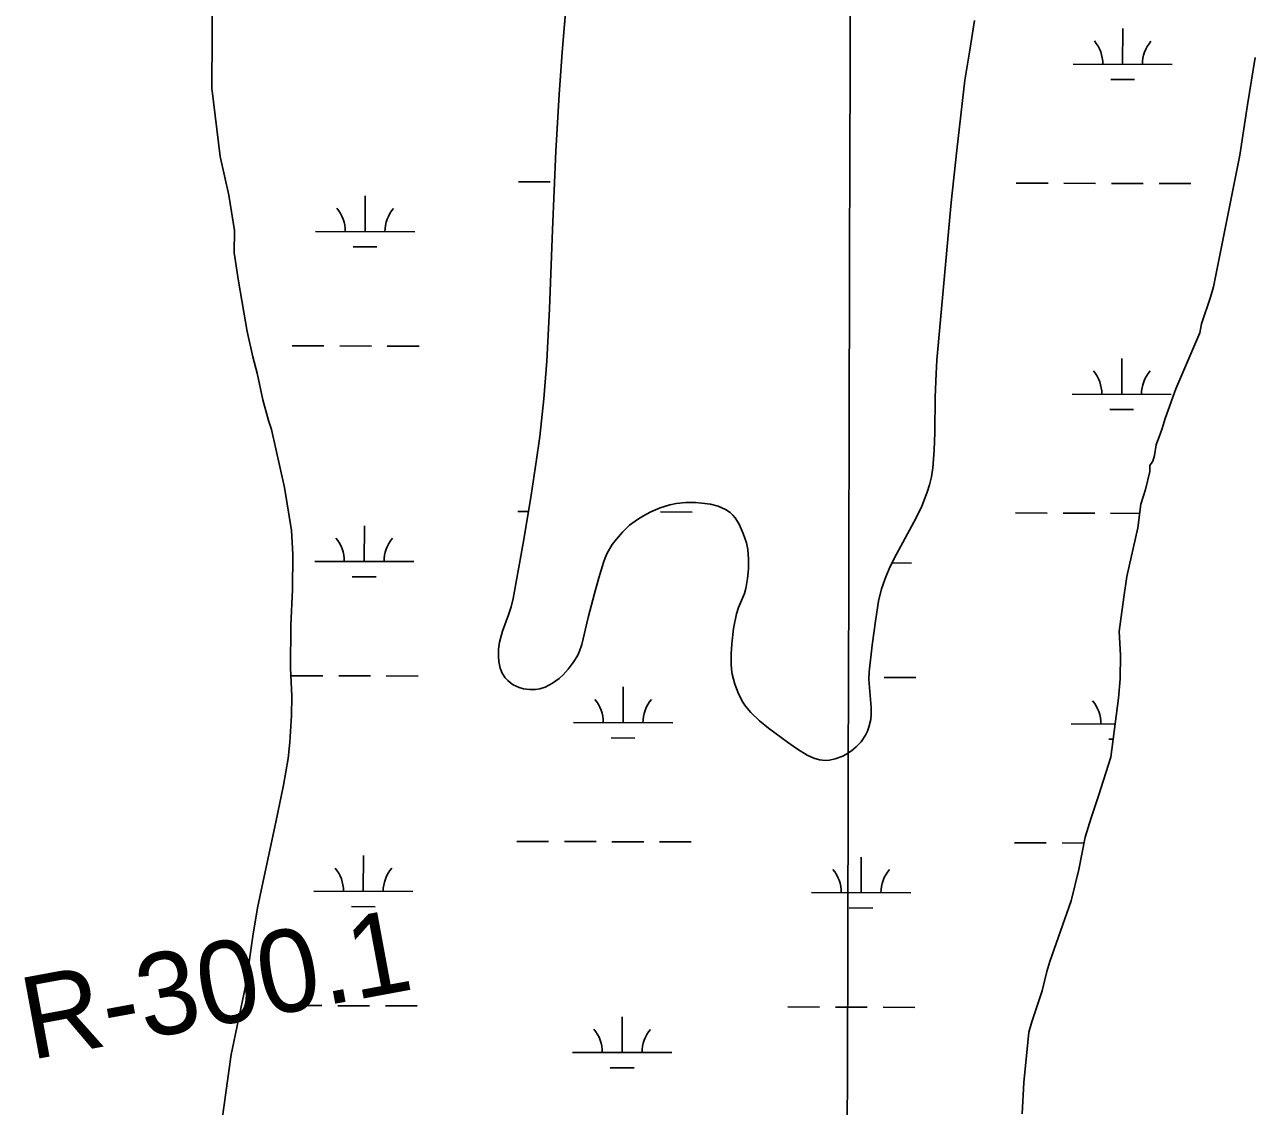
# Model space of a CAD drawing. Extents: x 3161665 to 3199565, y 885729 to 911164.
# Drawn here: x 3180736 to 3181970, y 895619 to 896710 of the extents above; entities that cross this region are included whole.
import ezdxf

# ---------------------------------------------------------------- set-up
doc = ezdxf.new("R2010")
doc.units = 0
for name, color, linetype in [('V-GRID-MAJR', 7, 'Continuous'), ('V-RIVR-RANG-IDEN', 7, 'Continuous'), ('V-SITE-VEGE', 7, 'Continuous'), ('V-TOPO-SHOR', 7, 'Continuous'), ('V-WETL-SWMP', 7, 'Continuous')]:
    doc.layers.add(name, color=color, linetype=linetype)

msp = doc.modelspace()

# ---------------------------------------------------------------- linework, layer by layer
at = {"layer": 'V-GRID-MAJR'}
msp.add_spline([(3181553.2, 891152.2), (3181570, 897211.5), (3181586.7, 903274.3), (3181603.5, 909337.1), (3181603.5, 909340.5)], degree=3, dxfattribs=at)
at = {"layer": 'V-SITE-VEGE'}
for p, q in [((3181278.3, 896682.2), (3181283.8, 896746.3)), ((3181694.2, 896714.2), (3181689.2, 896684.1)), ((3181275.2, 896639.4), (3181278.3, 896682.2)), ((3181689.2, 896684.1), (3181684.4, 896653.9)), ((3181684.4, 896653.9), (3181676.1, 896583.4)), ((3181271.8, 896582.3), (3181275.2, 896639.4)), ((3181268.5, 896502.9), (3181271.8, 896582.3)), ((3181676.1, 896583.4), (3181670.6, 896530.4)), ((3181670.6, 896530.4), (3181656.2, 896371.4)), ((3181265.5, 896423.4), (3181268.5, 896502.9)), ((3181262.8, 896370.5), (3181265.5, 896423.4)), ((3181259.8, 896332.4), (3181262.8, 896370.5)), ((3181656.2, 896371.4), (3181655.3, 896357.9)), ((3181655.3, 896357.9), (3181654.5, 896334.1)), ((3181255.6, 896294.4), (3181259.8, 896332.4)), ((3181654.5, 896334.1), (3181654.1, 896298.4)), ((3181252.2, 896269.1), (3181255.6, 896294.4)), ((3181654.1, 896298.4), (3181653.5, 896280.6)), ((3181653.5, 896280.6), (3181652.1, 896262.8)), ((3181247.1, 896235.4), (3181252.2, 896269.1)), ((3181652.1, 896262.8), (3181650.7, 896253.9)), ((3181648.7, 896245.7), (3181646.4, 896238.2)), ((3181650.7, 896253.9), (3181648.7, 896245.7)), ((3181239.6, 896190.7), (3181247.1, 896235.4)), ((3181646.4, 896238.2), (3181640.9, 896224.3)), ((3181367.6, 896218.5), (3181359.7, 896214.3)), ((3181377.1, 896222.5), (3181367.6, 896218.5)), ((3181386.7, 896225.5), (3181377.1, 896222.5)), ((3181393.3, 896226.8), (3181386.7, 896225.5)), ((3181402.9, 896227.9), (3181393.3, 896226.8)), ((3181412.7, 896228), (3181402.9, 896227.9)), ((3181419.2, 896227.4), (3181412.7, 896228)), ((3181427.8, 896226.1), (3181419.2, 896227.4)), ((3181435.5, 896224.1), (3181427.8, 896226.1)), ((3181442.8, 896220.8), (3181435.5, 896224.1)), ((3181447.5, 896217.7), (3181442.8, 896220.8)), ((3181450.4, 896215.1), (3181447.5, 896217.7)), ((3181640.9, 896224.3), (3181635.2, 896212.5)), ((3181354.1, 896210.9), (3181346.3, 896205)), ((3181359.7, 896214.3), (3181354.1, 896210.9)), ((3181452.8, 896212.4), (3181450.4, 896215.1)), ((3181456.6, 896206.2), (3181452.8, 896212.4)), ((3181460.9, 896196.7), (3181456.6, 896206.2)), ((3181635.2, 896212.5), (3181613.1, 896171.4)), ((3181339, 896198.1), (3181332.9, 896191)), ((3181346.3, 896205), (3181339, 896198.1)), ((3181464.1, 896187.1), (3181460.9, 896196.7)), ((3181229, 896131.1), (3181239.6, 896190.7)), ((3181328.8, 896185.5), (3181323.6, 896176.8)), ((3181332.9, 896191), (3181328.8, 896185.5)), ((3181465.4, 896180.5), (3181464.1, 896187.1)), ((3181321.6, 896172.2), (3181319.9, 896167.5)), ((3181323.6, 896176.8), (3181321.6, 896172.2)), ((3181466.3, 896170.8), (3181465.4, 896180.5)), ((3181466.2, 896161.2), (3181466.3, 896170.8)), ((3181613.1, 896171.4), (3181608, 896160.9)), ((3181319.9, 896167.5), (3181315.3, 896151.9)), ((3181465.3, 896151.2), (3181466.2, 896161.2)), ((3181608, 896160.9), (3181604.7, 896153)), ((3181315.3, 896151.9), (3181310.9, 896136.3)), ((3181463.5, 896141.2), (3181465.3, 896151.2)), ((3181604.7, 896153), (3181600.4, 896140.8)), ((3181310.9, 896136.3), (3181304.4, 896112.1)), ((3181456, 896122.2), (3181462, 896136.3)), ((3181462, 896136.3), (3181463.5, 896141.2)), ((3181600.4, 896140.8), (3181597.4, 896128.4)), ((3181224.2, 896114.5), (3181226.9, 896122.7)), ((3181226.9, 896122.7), (3181229, 896131.1)), ((3181453.9, 896115.7), (3181456, 896122.2)), ((3181597.4, 896128.4), (3181594.5, 896110.6)), ((3181218.2, 896098.2), (3181224.2, 896114.5)), ((3181304.4, 896112.1), (3181298.2, 896084.8)), ((3181451.1, 896100.7), (3181453.9, 896115.7)), ((3181594.5, 896110.6), (3181591, 896084)), ((3181214.9, 896087.2), (3181218.2, 896098.2)), ((3181449.2, 896085.5), (3181451.1, 896100.7)), ((3181213.9, 896080), (3181214.9, 896087.2)), ((3181298.2, 896084.8), (3181295.9, 896078.1)), ((3181448.6, 896075.2), (3181449.2, 896085.5)), ((3181591, 896084), (3181587.9, 896057.3)), ((3181213.9, 896072.5), (3181213.9, 896080)), ((3181214.5, 896067.5), (3181213.9, 896072.5)), ((3181293.6, 896073.4), (3181289.3, 896066.5)), ((3181295.9, 896078.1), (3181293.6, 896073.4)), ((3181448.6, 896064.8), (3181448.6, 896075.2)), ((3181215.9, 896061), (3181214.5, 896067.5)), ((3181217.8, 896055.9), (3181215.9, 896061)), ((3181284.3, 896059.8), (3181279.3, 896054.1)), ((3181289.3, 896066.5), (3181284.3, 896059.8)), ((3181449, 896059.8), (3181448.6, 896064.8)), ((3181449.8, 896054.8), (3181449, 896059.8)), ((3181587.9, 896057.3), (3181587.5, 896049.3)), ((3181220.7, 896051.2), (3181217.8, 896055.9)), ((3181223.4, 896048.3), (3181220.7, 896051.2)), ((3181226.2, 896046), (3181223.4, 896048.3)), ((3181229, 896044.1), (3181226.2, 896046)), ((3181268.5, 896045.7), (3181261.1, 896041.8)), ((3181275.2, 896050.4), (3181268.5, 896045.7)), ((3181279.3, 896054.1), (3181275.2, 896050.4)), ((3181452.5, 896044.8), (3181449.8, 896054.8)), ((3181455.7, 896036), (3181452.5, 896044.8)), ((3181587.5, 896049.3), (3181589.8, 896021.3)), ((3181234.9, 896041.4), (3181229, 896044.1)), ((3181239.1, 896040.1), (3181234.9, 896041.4)), ((3181245.2, 896039.2), (3181239.1, 896040.1)), ((3181251.5, 896039.2), (3181245.2, 896039.2)), ((3181255.7, 896039.9), (3181251.5, 896039.2)), ((3181261.1, 896041.8), (3181255.7, 896039.9)), ((3181459.8, 896027.7), (3181455.7, 896036)), ((3181463.1, 896022.5), (3181459.8, 896027.7)), ((3181468.4, 896016), (3181463.1, 896022.5)), ((3181589.8, 896021.3), (3181589.8, 896014.3)), ((3181477.1, 896007.6), (3181468.4, 896016)), ((3181589.4, 896009.1), (3181587.6, 896001.2)), ((3181589.8, 896014.3), (3181589.4, 896009.1)), ((3181486.2, 896000.2), (3181477.1, 896007.6)), ((3181505.5, 895986.1), (3181486.2, 896000.2)), ((3181586.2, 895997.3), (3181584.3, 895993.4)), ((3181587.6, 896001.2), (3181586.2, 895997.3)), ((3181515.4, 895979.3), (3181505.5, 895986.1)), ((3181579.7, 895986.6), (3181574.8, 895981.4)), ((3181584.3, 895993.4), (3181579.7, 895986.6)), ((3181525.4, 895973.2), (3181515.4, 895979.3)), ((3181532.1, 895970), (3181525.4, 895973.2)), ((3181561.2, 895972.2), (3181553.6, 895969.4)), ((3181565.4, 895974.4), (3181561.2, 895972.2)), ((3181570, 895977.4), (3181565.4, 895974.4)), ((3181574.8, 895981.4), (3181570, 895977.4)), ((3181537.7, 895968.3), (3181532.1, 895970)), ((3181543.7, 895967.8), (3181537.7, 895968.3)), ((3181547.9, 895968.2), (3181543.7, 895967.8)), ((3181553.6, 895969.4), (3181547.9, 895968.2))]:
    msp.add_line(p, q, dxfattribs=at)
at = {"layer": 'V-TOPO-SHOR'}
for points in [[(3181377.1, 896222.5), (3181367.6, 896218.5), (3181359.7, 896214.3), (3181354.1, 896210.9), (3181346.3, 896205), (3181339, 896198.1), (3181332.9, 896191), (3181328.8, 896185.5), (3181323.6, 896176.8), (3181321.6, 896172.2), (3181319.9, 896167.5), (3181315.3, 896151.9), (3181310.9, 896136.3), (3181304.4, 896112.1), (3181298.2, 896084.8), (3181295.9, 896078.1), (3181293.6, 896073.4), (3181289.3, 896066.5), (3181284.3, 896059.8), (3181279.3, 896054.1), (3181275.2, 896050.4), (3181268.5, 896045.7), (3181261.1, 896041.8), (3181255.7, 896039.9), (3181251.5, 896039.2), (3181245.2, 896039.2), (3181239.1, 896040.1), (3181234.9, 896041.4), (3181229, 896044.1), (3181226.2, 896046), (3181223.4, 896048.3), (3181220.7, 896051.2), (3181217.8, 896055.9), (3181215.9, 896061), (3181214.5, 896067.5), (3181213.9, 896072.5), (3181213.9, 896080), (3181214.9, 896087.2), (3181218.2, 896098.2), (3181224.2, 896114.5), (3181226.9, 896122.7), (3181229, 896131.1), (3181239.6, 896190.7), (3181247.1, 896235.4), (3181252.2, 896269.1), (3181255.6, 896294.4), (3181259.8, 896332.4), (3181262.8, 896370.5), (3181265.5, 896423.4), (3181268.5, 896502.9), (3181271.8, 896582.3), (3181275.2, 896639.4), (3181278.3, 896682.2), (3181283.8, 896746.3)], [(3181694.2, 896714.2), (3181689.2, 896684.1), (3181684.4, 896653.9), (3181676.1, 896583.4), (3181670.6, 896530.4), (3181656.2, 896371.4), (3181655.3, 896357.9), (3181654.5, 896334.1), (3181654.1, 896298.4), (3181653.5, 896280.6), (3181652.1, 896262.8), (3181650.7, 896253.9), (3181648.7, 896245.7), (3181646.4, 896238.2), (3181640.9, 896224.3), (3181635.2, 896212.5), (3181613.1, 896171.4), (3181608, 896160.9), (3181604.7, 896153), (3181600.4, 896140.8), (3181597.4, 896128.4), (3181594.5, 896110.6), (3181591, 896084), (3181587.9, 896057.3), (3181587.5, 896049.3), (3181589.8, 896021.3), (3181589.8, 896014.3), (3181589.4, 896009.1), (3181587.6, 896001.2), (3181586.2, 895997.3), (3181584.3, 895993.4), (3181579.7, 895986.6), (3181574.8, 895981.4), (3181570, 895977.4), (3181565.4, 895974.4), (3181561.2, 895972.2), (3181553.6, 895969.4), (3181547.9, 895968.2), (3181543.7, 895967.8), (3181537.7, 895968.3), (3181532.1, 895970), (3181525.4, 895973.2), (3181515.4, 895979.3), (3181505.5, 895986.1), (3181486.2, 896000.2), (3181477.1, 896007.6), (3181468.4, 896016), (3181463.1, 896022.5), (3181459.8, 896027.7), (3181455.7, 896036), (3181452.5, 896044.8), (3181449.8, 896054.8), (3181449, 896059.8), (3181448.6, 896064.8), (3181448.6, 896075.2), (3181449.2, 896085.5), (3181451.1, 896100.7), (3181453.9, 896115.7), (3181456, 896122.2), (3181462, 896136.3), (3181463.5, 896141.2), (3181465.3, 896151.2), (3181466.2, 896161.2), (3181466.3, 896170.8), (3181465.4, 896180.5), (3181464.1, 896187.1), (3181460.9, 896196.7), (3181456.6, 896206.2), (3181452.8, 896212.4), (3181450.4, 896215.1), (3181447.5, 896217.7), (3181442.8, 896220.8), (3181435.5, 896224.1), (3181427.8, 896226.1), (3181419.2, 896227.4), (3181412.7, 896228), (3181402.9, 896227.9), (3181393.3, 896226.8), (3181386.7, 896225.5), (3181377.1, 896222.5)]]:
    msp.add_lwpolyline(points, dxfattribs=at)
at = {"layer": 'V-WETL-SWMP'}
for p, q in [((3181843.4, 896669.8), (3181843.5, 896705.8)), ((3181793.4, 896670), (3181893.4, 896669.7)), ((3181831.4, 896654.4), (3181855.4, 896654.4)), ((3181234.3, 896551.4), (3181266.3, 896551.3)), ((3181736.2, 896550), (3181768.2, 896550)), ((3181784.2, 896549.9), (3181816.2, 896549.8)), ((3181832.2, 896549.8), (3181864.2, 896549.7)), ((3181880.2, 896549.7), (3181912.2, 896549.6)), ((3181079.6, 896501.1), (3181079.7, 896537.1)), ((3181029.6, 896501.3), (3181129.6, 896501)), ((3181067.5, 896485.7), (3181091.5, 896485.7)), ((3181005.9, 896385.9), (3181037.9, 896385.8)), ((3181053.9, 896385.8), (3181085.9, 896385.7)), ((3181101.9, 896385.6), (3181133.9, 896385.5)), ((3181842.5, 896337.2), (3181842.6, 896373.2)), ((3181792.5, 896337.3), (3181892.5, 896337)), ((3181830.4, 896321.8), (3181854.4, 896321.7)), ((3181233.4, 896218.8), (3181244.3, 896218.7)), ((3181377.4, 896218.4), (3181409.4, 896218.3)), ((3181735.3, 896217.4), (3181767.3, 896217.3)), ((3181783.3, 896217.2), (3181815.3, 896217.2)), ((3181831.3, 896217.1), (3181860.5, 896217)), ((3181078.7, 896168.4), (3181078.8, 896204.4)), ((3181028.7, 896168.6), (3181128.7, 896168.3)), ((3181610.9, 896167), (3181630.6, 896166.9)), ((3181066.6, 896153), (3181090.6, 896153)), ((3181004.9, 896053.2), (3181036.9, 896053.1)), ((3181052.9, 896053.1), (3181084.9, 896053)), ((3181100.9, 896053), (3181132.9, 896052.9)), ((3181602.8, 896051.6), (3181634.8, 896051.5)), ((3181339.7, 896005.9), (3181339.8, 896041.9)), ((3181289.7, 896006), (3181389.7, 896005.7)), ((3181791.6, 896004.6), (3181835.9, 896004.5)), ((3181327.6, 895990.5), (3181351.6, 895990.4)), ((3181829.5, 895989.1), (3181833.9, 895989.1)), ((3181232.5, 895886.1), (3181264.5, 895886)), ((3181280.5, 895886), (3181312.5, 895885.9)), ((3181328.5, 895885.8), (3181360.5, 895885.7)), ((3181376.5, 895885.7), (3181408.5, 895885.6)), ((3181734.4, 895884.7), (3181766.4, 895884.6)), ((3181782.4, 895884.6), (3181804.3, 895884.5)), ((3181077.7, 895835.8), (3181077.8, 895871.8)), ((3181579.7, 895834.4), (3181579.8, 895870.4)), ((3181027.7, 895835.9), (3181127.7, 895835.6)), ((3181529.7, 895834.5), (3181629.7, 895834.2)), ((3181065.7, 895820.4), (3181089.7, 895820.3)), ((3181567.6, 895819), (3181591.6, 895818.9)), ((3181004, 895720.5), (3181036, 895720.5)), ((3181052, 895720.4), (3181084, 895720.3)), ((3181100, 895720.3), (3181132, 895720.2)), ((3181505.9, 895719.2), (3181537.9, 895719.1)), ((3181553.9, 895719), (3181585.9, 895718.9)), ((3181601.9, 895718.9), (3181633.9, 895718.8)), ((3181338.7, 895673.2), (3181338.8, 895709.2)), ((3181288.7, 895673.3), (3181388.7, 895673.1)), ((3181326.7, 895657.8), (3181350.7, 895657.7))]:
    msp.add_line(p, q, dxfattribs=at)
for points in [[(3180931.9, 895581.7), (3180944.6, 895671.3), (3180958.5, 895738.4), (3180961.6, 895757.8), (3180964.8, 895778.7), (3180966.4, 895790.7), (3180971.1, 895819), (3180975.7, 895841.4), (3180989.6, 895905.6), (3180997.4, 895942.9), (3181002.1, 895969.7), (3181003.7, 895986.1), (3181005.4, 896013), (3181005.5, 896032.5), (3181004.3, 896060.9), (3181004.6, 896104.2), (3181006.3, 896140), (3181006.6, 896175.9), (3181005.3, 896199.8), (3180998.1, 896243.2), (3180985.1, 896301.6), (3180982.2, 896310.6), (3180976.4, 896331.5), (3180970.6, 896358.5), (3180966.3, 896375), (3180960.5, 896400.4), (3180951.9, 896451.3), (3180947.6, 896479.7), (3180947.8, 896502.1), (3180942.1, 896538), (3180933.4, 896576.9), (3180924.9, 896645.7), (3180925.7, 896751.8)], [(3181283.8, 896746.3), (3181278.3, 896682.2), (3181275.2, 896639.4), (3181271.8, 896582.3), (3181268.5, 896502.9), (3181265.5, 896423.4), (3181262.8, 896370.5), (3181259.8, 896332.4), (3181255.6, 896294.4), (3181252.2, 896269.1), (3181247.1, 896235.4), (3181239.6, 896190.7), (3181229, 896131.1), (3181226.9, 896122.7), (3181224.2, 896114.5), (3181218.2, 896098.2), (3181214.9, 896087.2), (3181213.9, 896080), (3181213.9, 896072.5), (3181214.5, 896067.5), (3181215.9, 896061), (3181217.8, 896055.9), (3181220.7, 896051.2), (3181223.4, 896048.3), (3181226.2, 896046), (3181229, 896044.1), (3181234.9, 896041.4), (3181239.1, 896040.1), (3181245.2, 896039.2), (3181251.5, 896039.2), (3181255.7, 896039.9), (3181261.1, 896041.8), (3181268.5, 896045.7), (3181275.2, 896050.4), (3181279.3, 896054.1), (3181284.3, 896059.8), (3181289.3, 896066.5), (3181293.6, 896073.4), (3181295.9, 896078.1), (3181298.2, 896084.8), (3181304.4, 896112.1), (3181310.9, 896136.3), (3181315.3, 896151.9), (3181319.9, 896167.5), (3181321.6, 896172.2), (3181323.6, 896176.8), (3181328.8, 896185.5), (3181332.9, 896191), (3181339, 896198.1), (3181346.3, 896205), (3181354.1, 896210.9), (3181359.7, 896214.3), (3181367.6, 896218.5), (3181377.1, 896222.5), (3181386.7, 896225.5), (3181393.3, 896226.8), (3181402.9, 896227.9), (3181412.7, 896228), (3181419.2, 896227.4), (3181427.8, 896226.1), (3181435.5, 896224.1), (3181442.8, 896220.8), (3181447.5, 896217.7), (3181450.4, 896215.1), (3181452.8, 896212.4), (3181456.6, 896206.2), (3181460.9, 896196.7), (3181464.1, 896187.1), (3181465.4, 896180.5), (3181466.3, 896170.8), (3181466.2, 896161.2), (3181465.3, 896151.2), (3181463.5, 896141.2), (3181462, 896136.3), (3181456, 896122.2), (3181453.9, 896115.7), (3181451.1, 896100.7), (3181449.2, 896085.5), (3181448.6, 896075.2), (3181448.6, 896064.8), (3181449, 896059.8), (3181449.8, 896054.8)], [(3181449.8, 896054.8), (3181452.5, 896044.8), (3181455.7, 896036), (3181459.8, 896027.7), (3181463.1, 896022.5), (3181468.4, 896016), (3181477.1, 896007.6), (3181486.2, 896000.2), (3181505.5, 895986.1), (3181515.4, 895979.3), (3181525.4, 895973.2), (3181532.1, 895970), (3181537.7, 895968.3), (3181543.7, 895967.8), (3181547.9, 895968.2), (3181553.6, 895969.4), (3181561.2, 895972.2), (3181565.4, 895974.4), (3181570, 895977.4), (3181574.8, 895981.4), (3181579.7, 895986.6), (3181584.3, 895993.4), (3181586.2, 895997.3), (3181587.6, 896001.2), (3181589.4, 896009.1), (3181589.8, 896014.3), (3181589.8, 896021.3), (3181587.5, 896049.3), (3181587.9, 896057.3), (3181591, 896084), (3181594.5, 896110.6), (3181597.4, 896128.4), (3181600.4, 896140.8), (3181604.7, 896153), (3181608, 896160.9), (3181613.1, 896171.4), (3181635.2, 896212.5), (3181640.9, 896224.3), (3181646.4, 896238.2), (3181648.7, 896245.7), (3181650.7, 896253.9), (3181652.1, 896262.8), (3181653.5, 896280.6), (3181654.1, 896298.4), (3181654.5, 896334.1), (3181655.3, 896357.9), (3181656.2, 896371.4), (3181670.6, 896530.4), (3181676.1, 896583.4), (3181684.4, 896653.9), (3181689.2, 896684.1), (3181694.2, 896714.2)], [(3181977.2, 896676.7), (3181969.4, 896629), (3181961.5, 896578.2), (3181935.1, 896445.4), (3181932.1, 896435), (3181922.9, 896408.2), (3181921.3, 896399.2), (3181897, 896342.6), (3181886.3, 896312.8), (3181883.2, 896302.4), (3181881.7, 896297.9), (3181877.1, 896286), (3181875.6, 896275.5), (3181874, 896269.5), (3181871, 896265.1), (3181871, 896259.1), (3181866.4, 896241.2), (3181861.8, 896226.3), (3181858.6, 896202.4), (3181847.8, 896153.2), (3181844.6, 896132.3), (3181839.9, 896097.9), (3181841.2, 896074), (3181841, 896050.1), (3181839.4, 896030.7), (3181831.5, 895971), (3181819.2, 895932.2), (3181811.6, 895909.9), (3181805.5, 895890.5), (3181799.2, 895857.7), (3181791.5, 895826.3), (3181770.1, 895765.2), (3181767.1, 895754.8), (3181762.4, 895735.4), (3181751.8, 895704.1), (3181748.7, 895693.7), (3181743.8, 895642.9), (3181742.1, 895611.5)]]:
    msp.add_lwpolyline(points, dxfattribs=at)
for centre, start, end in [((3181788.2, 896670.5), 359.0698, 40.6135), ((3181898.6, 896670.1), 139.0698, 180.6135), ((3181024.3, 896501.7), 359.0698, 40.6135), ((3181134.8, 896501.4), 139.0698, 180.6135), ((3181787.2, 896337.8), 359.0698, 40.6135), ((3181897.7, 896337.5), 139.0698, 180.6135), ((3181023.4, 896169.1), 359.0698, 40.6135), ((3181133.9, 896168.8), 139.0698, 180.6135), ((3181284.4, 896006.5), 359.0698, 40.6135), ((3181394.9, 896006.2), 139.0698, 180.6135), ((3181786.3, 896005.1), 359.0698, 40.6135), ((3181022.5, 895836.4), 359.0698, 40.6135), ((3181133, 895836.1), 139.0698, 180.6135), ((3181524.4, 895835), 359.0698, 40.6135), ((3181634.9, 895834.7), 139.0698, 180.6135), ((3181283.5, 895673.8), 359.0698, 40.6135), ((3181394, 895673.5), 139.0698, 180.6135)]:
    msp.add_arc(centre, 35.2, start, end, dxfattribs=at)

# ---------------------------------------------------------------- texts
at = {"layer": 'V-RIVR-RANG-IDEN'}
msp.add_text('R-300.1', height=83, rotation=10.487, dxfattribs=at).set_placement((3180742.2, 895665.6))

doc.saveas('drawing.dxf')
